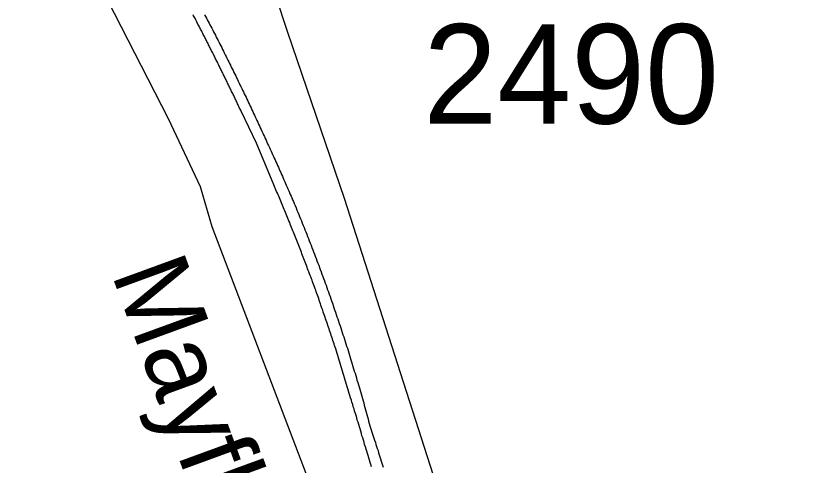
# Model space of a CAD drawing. Extents: x 1364363 to 1407445, y 538563 to 573342.
# Drawn here: x 1378365 to 1379352, y 550369 to 550934 of the extents above; entities that cross this region are included whole.
import ezdxf

# ---------------------------------------------------------------- set-up
doc = ezdxf.new("R2010")
doc.units = 0
for name, color, linetype in [('Exist Railroad Mainline', 7, 'Continuous'), ('Exist Railroad Siding', 7, 'Continuous'), ('Exist Road Secondary Type 51 Attributed', 7, 'Continuous'), ('Exist Road Secondary Type 51 Label', 7, 'Continuous'), ('Exist Road Secondary Type 51 Number Label', 7, 'Continuous')]:
    doc.layers.add(name, color=color, linetype=linetype)

msp = doc.modelspace()

# ---------------------------------------------------------------- linework, layer by layer
at = {"layer": 'Exist Railroad Mainline'}
for points in [[(1378649.02, 550814.08), (1378648.41, 550815.37), (1378647.79, 550816.7), (1378647.07, 550817.98), (1378646.46, 550819.31), (1378645.84, 550820.65), (1378645.23, 550821.93), (1378644.61, 550823.26), (1378644, 550824.54), (1378643.38, 550825.88), (1378642.77, 550827.21), (1378642.15, 550828.49), (1378641.54, 550829.82), (1378640.92, 550831.1), (1378640.21, 550832.44), (1378639.59, 550833.77), (1378638.98, 550835.05), (1378638.36, 550836.38), (1378637.74, 550837.67), (1378637.03, 550839), (1378636.41, 550840.33), (1378635.8, 550841.61), (1378635.08, 550842.95), (1378634.46, 550844.23), (1378633.85, 550845.56), (1378633.23, 550846.89), (1378632.62, 550848.17), (1378632, 550849.51), (1378631.39, 550850.79), (1378630.77, 550852.12), (1378630.16, 550853.35), (1378629.34, 550854.68), (1378628.72, 550856.02), (1378628.11, 550857.3), (1378627.49, 550858.63), (1378626.88, 550859.91), (1378626.26, 550861.25), (1378625.65, 550862.58), (1378624.83, 550863.86), (1378624.21, 550865.19), (1378623.6, 550866.42), (1378622.98, 550867.76), (1378622.37, 550869.04), (1378621.75, 550870.37), (1378621.03, 550871.7), (1378620.42, 550872.99), (1378619.7, 550874.32), (1378619.08, 550875.55), (1378618.47, 550876.88), (1378617.75, 550878.16), (1378617.14, 550879.5), (1378616.52, 550880.83), (1378615.91, 550882.11), (1378615.29, 550883.39), (1378614.47, 550884.67), (1378613.86, 550886.01), (1378613.24, 550887.29), (1378612.63, 550888.62), (1378611.91, 550889.85), (1378611.29, 550891.18), (1378610.58, 550892.52), (1378609.96, 550893.8), (1378609.24, 550895.08), (1378608.63, 550896.36), (1378608.01, 550897.69), (1378607.4, 550898.98), (1378606.58, 550900.31), (1378605.96, 550901.54), (1378605.35, 550902.87), (1378604.63, 550904.2), (1378604.01, 550905.44), (1378603.4, 550906.77), (1378602.78, 550908.05), (1378601.96, 550909.38), (1378601.35, 550910.61), (1378600.73, 550911.95), (1378600.02, 550913.23), (1378599.4, 550914.51), (1378598.78, 550915.79), (1378597.96, 550917.12), (1378597.35, 550918.46), (1378596.73, 550919.69), (1378596.02, 550921.02), (1378595.4, 550922.3), (1378594.58, 550923.58), (1378593.97, 550924.86), (1378593.35, 550926.2), (1378592.63, 550927.43), (1378592.02, 550928.76), (1378591.4, 550929.99), (1378590.58, 550931.32), (1378589.97, 550932.6), (1378589.25, 550933.89), (1378588.63, 550935.17)], [(1378690.14, 550721.45), (1378668.3, 550773.79), (1378649.02, 550814.08)], [(1378767.95, 550515.17), (1378767.24, 550517.32), (1378766.62, 550519.42), (1378765.9, 550521.48), (1378765.29, 550523.63), (1378764.47, 550525.73), (1378763.85, 550527.88), (1378763.13, 550529.98), (1378762.42, 550532.14), (1378761.8, 550534.19), (1378760.98, 550536.29), (1378760.26, 550538.44), (1378759.65, 550540.55), (1378758.83, 550542.7), (1378758.11, 550544.75), (1378757.5, 550546.85), (1378756.78, 550549), (1378755.96, 550551.11), (1378755.24, 550553.21), (1378754.52, 550555.31), (1378753.91, 550557.46), (1378753.09, 550559.51), (1378752.37, 550561.61), (1378751.65, 550563.77), (1378750.83, 550565.82), (1378750.11, 550567.92), (1378749.4, 550570.07), (1378748.78, 550572.12), (1378747.96, 550574.23), (1378747.24, 550576.33), (1378746.52, 550578.43), (1378745.7, 550580.58), (1378744.99, 550582.63), (1378744.27, 550584.73), (1378743.45, 550586.84), (1378742.73, 550588.94), (1378741.91, 550590.99), (1378741.09, 550593.14), (1378740.37, 550595.19), (1378739.66, 550597.29), (1378738.84, 550599.4), (1378738.12, 550601.5), (1378737.4, 550603.55), (1378736.58, 550605.7), (1378735.76, 550607.75), (1378735.04, 550609.8), (1378734.22, 550611.95), (1378733.5, 550614.01), (1378732.58, 550616.11), (1378731.86, 550618.21), (1378731.15, 550620.26), (1378730.22, 550622.36), (1378729.51, 550624.46), (1378728.79, 550626.51), (1378727.87, 550628.61), (1378727.15, 550630.67), (1378726.33, 550632.77), (1378725.51, 550634.82), (1378724.79, 550636.92), (1378723.87, 550639.02), (1378723.15, 550641.07), (1378722.33, 550643.12), (1378721.51, 550645.17), (1378720.79, 550647.33), (1378719.87, 550649.38), (1378719.05, 550651.43), (1378718.23, 550653.48), (1378717.41, 550655.58), (1378716.59, 550657.63), (1378715.77, 550659.73), (1378715.05, 550661.83), (1378714.13, 550663.88), (1378713.2, 550665.93), (1378712.49, 550667.98), (1378711.67, 550670.09), (1378710.74, 550672.14), (1378710.03, 550674.19), (1378709.1, 550676.24), (1378708.28, 550678.29), (1378707.36, 550680.39), (1378706.64, 550682.44), (1378705.72, 550684.49), (1378704.9, 550686.54), (1378703.98, 550688.64), (1378703.16, 550690.69), (1378702.34, 550692.75), (1378701.52, 550694.8), (1378700.59, 550696.79), (1378699.77, 550698.9), (1378698.85, 550700.95), (1378698.03, 550703), (1378697.11, 550705.05), (1378696.29, 550707.15), (1378695.36, 550709.15), (1378694.54, 550711.2), (1378693.62, 550713.25), (1378692.8, 550715.3), (1378691.88, 550717.35), (1378690.96, 550719.35), (1378690.14, 550721.45)], [(1378812.76, 550367.07), (1378812.04, 550369.89), (1378811.12, 550372.61), (1378810.3, 550375.43), (1378809.48, 550378.25), (1378808.66, 550381.07), (1378807.73, 550383.83), (1378806.91, 550386.6), (1378806.09, 550389.42), (1378805.27, 550392.24), (1378804.35, 550395.01), (1378803.63, 550397.83), (1378802.71, 550400.65), (1378801.89, 550403.42), (1378800.97, 550406.19), (1378800.25, 550409), (1378799.33, 550411.82), (1378798.51, 550414.64), (1378797.79, 550417.36), (1378796.87, 550420.18), (1378796.04, 550423), (1378795.12, 550425.82), (1378794.4, 550428.59), (1378793.48, 550431.35), (1378792.66, 550434.17), (1378791.74, 550436.94), (1378791.02, 550439.76), (1378790.1, 550442.58), (1378789.28, 550445.35), (1378788.36, 550448.12), (1378787.64, 550450.94), (1378786.72, 550453.76), (1378785.89, 550456.53), (1378784.97, 550459.29), (1378784.15, 550462.11), (1378783.33, 550464.88), (1378782.51, 550467.7), (1378781.59, 550470.52), (1378780.77, 550473.29), (1378779.85, 550476.06), (1378779.13, 550478.88), (1378778.21, 550481.7), (1378777.39, 550484.41), (1378776.46, 550487.23), (1378775.64, 550490.05), (1378774.92, 550492.82), (1378774, 550495.64), (1378773.08, 550498.46), (1378772.26, 550501.18), (1378771.34, 550503.99), (1378770.52, 550506.81), (1378769.8, 550509.58), (1378768.88, 550512.35), (1378767.95, 550515.17)]]:
    msp.add_lwpolyline(points, dxfattribs=at)
at = {"layer": 'Exist Railroad Siding'}
for points in [[(1378602.99, 550935.12), (1378604.12, 550933.01), (1378605.24, 550930.91), (1378606.37, 550928.86), (1378607.5, 550926.81), (1378608.63, 550924.71), (1378609.76, 550922.61), (1378610.99, 550920.56)], [(1378610.99, 550920.56), (1378612.11, 550918.3), (1378613.24, 550916.15), (1378614.37, 550913.94), (1378615.5, 550911.69), (1378616.62, 550909.49), (1378617.75, 550907.23), (1378618.88, 550905.08), (1378620.01, 550902.82), (1378621.14, 550900.62), (1378622.26, 550898.41), (1378623.39, 550896.21), (1378624.52, 550894), (1378625.54, 550891.75), (1378626.67, 550889.54), (1378627.8, 550887.29), (1378628.82, 550885.14), (1378629.95, 550882.88), (1378631.08, 550880.62), (1378632.21, 550878.42), (1378633.34, 550876.16), (1378634.36, 550874.01), (1378635.49, 550871.76), (1378636.62, 550869.5), (1378637.74, 550867.3), (1378638.77, 550865.04), (1378639.9, 550862.84), (1378641.03, 550860.63), (1378642.15, 550858.38), (1378643.08, 550856.12), (1378644.2, 550853.92), (1378645.33, 550851.71), (1378646.46, 550849.46), (1378647.48, 550847.25), (1378648.61, 550845), (1378649.74, 550842.74), (1378650.77, 550840.49), (1378651.89, 550838.23), (1378652.92, 550836.08), (1378654.05, 550833.82), (1378655.17, 550831.57), (1378656.1, 550829.31), (1378657.22, 550827.05), (1378658.25, 550824.8), (1378659.38, 550822.65), (1378660.4, 550820.39), (1378661.53, 550818.13), (1378662.45, 550815.88), (1378663.58, 550813.62), (1378664.61, 550811.37), (1378665.73, 550809.11), (1378666.76, 550806.86), (1378667.89, 550804.6), (1378668.91, 550802.4), (1378669.84, 550800.14), (1378670.96, 550797.89), (1378671.99, 550795.63), (1378673.12, 550793.37), (1378674.14, 550791.12), (1378675.17, 550788.86), (1378676.29, 550786.61), (1378677.22, 550784.35), (1378678.24, 550782.15), (1378679.37, 550779.89), (1378680.4, 550777.64), (1378681.42, 550775.33), (1378682.34, 550773.07), (1378683.47, 550770.82), (1378684.5, 550768.56), (1378685.52, 550766.31), (1378686.55, 550764.05), (1378687.67, 550761.8), (1378688.6, 550759.49), (1378689.62, 550757.23), (1378690.65, 550754.98), (1378691.67, 550752.77), (1378692.6, 550750.42), (1378693.72, 550748.21), (1378694.75, 550745.96), (1378695.77, 550743.7), (1378696.8, 550741.39), (1378697.72, 550739.14), (1378698.75, 550736.88), (1378699.77, 550734.58), (1378700.8, 550732.32), (1378701.72, 550730.06), (1378702.75, 550727.76), (1378703.77, 550725.5), (1378704.8, 550723.25), (1378705.72, 550720.94), (1378706.74, 550718.68), (1378707.77, 550716.38), (1378708.8, 550714.12), (1378709.72, 550711.87), (1378710.74, 550709.56), (1378711.77, 550707.3), (1378712.79, 550705), (1378713.61, 550702.74), (1378714.64, 550700.43), (1378715.66, 550698.18)], [(1378715.66, 550698.18), (1378716.79, 550695.46), (1378718.02, 550692.69), (1378719.15, 550689.87), (1378720.28, 550687.11), (1378721.41, 550684.39), (1378722.53, 550681.62), (1378723.66, 550678.85), (1378724.79, 550676.08), (1378725.92, 550673.32), (1378727.04, 550670.55), (1378728.17, 550667.83), (1378729.3, 550665.01), (1378730.33, 550662.24), (1378731.45, 550659.42), (1378732.48, 550656.71), (1378733.61, 550653.89), (1378734.73, 550651.12), (1378735.86, 550648.35), (1378736.89, 550645.58), (1378738.02, 550642.76), (1378739.04, 550640), (1378740.17, 550637.18), (1378741.3, 550634.46), (1378742.22, 550631.64), (1378743.35, 550628.82), (1378744.37, 550626.05), (1378745.4, 550623.23), (1378746.52, 550620.41), (1378747.55, 550617.64), (1378748.58, 550614.88), (1378749.6, 550612.06), (1378750.63, 550609.24), (1378751.65, 550606.42), (1378752.78, 550603.65), (1378753.7, 550600.83), (1378754.73, 550598.01), (1378755.75, 550595.24), (1378756.78, 550592.42), (1378757.7, 550589.6), (1378758.73, 550586.84), (1378759.75, 550584.02), (1378760.78, 550581.15), (1378761.8, 550578.33), (1378762.72, 550575.51), (1378763.75, 550572.69), (1378764.77, 550569.87), (1378765.59, 550567.05), (1378766.62, 550564.23), (1378767.65, 550561.36), (1378768.67, 550558.54), (1378769.49, 550555.77), (1378770.52, 550552.95), (1378771.54, 550550.08), (1378772.36, 550547.26), (1378773.39, 550544.44), (1378774.21, 550541.57), (1378775.23, 550538.75), (1378776.15, 550535.93), (1378777.08, 550533.06), (1378778, 550530.24), (1378778.92, 550527.37), (1378779.85, 550524.55), (1378780.77, 550521.68), (1378781.59, 550518.86), (1378782.61, 550515.99), (1378783.54, 550513.17), (1378784.36, 550510.3), (1378785.28, 550507.48), (1378786.1, 550504.61), (1378787.02, 550501.74), (1378787.84, 550498.92), (1378788.77, 550496.05), (1378789.59, 550493.18), (1378790.51, 550490.36), (1378791.33, 550487.49), (1378792.25, 550484.62), (1378793.17, 550481.75), (1378793.99, 550478.88), (1378794.71, 550476.06), (1378795.63, 550473.19), (1378796.46, 550470.31), (1378797.38, 550467.44), (1378798.1, 550464.57), (1378799.02, 550461.7), (1378799.84, 550458.83), (1378800.66, 550455.96), (1378801.48, 550453.04), (1378802.3, 550450.17), (1378803.12, 550447.3), (1378803.84, 550444.43), (1378804.66, 550441.56), (1378805.48, 550438.69), (1378806.3, 550435.82), (1378807.02, 550432.94), (1378807.84, 550430.07), (1378808.66, 550427.2), (1378809.37, 550424.33), (1378810.09, 550421.46), (1378811.01, 550418.49)], [(1378811.01, 550418.49), (1378811.73, 550415.93), (1378812.65, 550413.36), (1378813.47, 550410.75), (1378814.4, 550408.18), (1378815.22, 550405.57), (1378816.04, 550402.96), (1378816.86, 550400.39), (1378817.78, 550397.73), (1378818.6, 550395.16), (1378819.42, 550392.55), (1378820.24, 550389.99), (1378821.16, 550387.37), (1378821.88, 550384.76), (1378822.7, 550382.19), (1378823.62, 550379.58), (1378824.34, 550376.91), (1378825.26, 550374.35), (1378825.98, 550371.74), (1378826.91, 550369.12), (1378827.62, 550366.56)]]:
    msp.add_lwpolyline(points, dxfattribs=at)
at = {"layer": 'Exist Road Secondary Type 51 Attributed'}
for points in [[(1378382.35, 551904.12), (1378429.78, 551811.86), (1378473.75, 551674.16), (1378543.71, 551422.65), (1378610.69, 551208.68), (1378661.13, 551053.31), (1378707.39, 550913.34), (1378778.53, 550704.8), (1378942.41, 550194.7), (1378990.85, 550031.69), (1379059.72, 549823.15), (1379089.99, 549724.76), (1379170.92, 549598.91), (1379210.9, 549552.37), (1379251.99, 549499.77), (1379372.32, 549398.37), (1379560.73, 549245.93), (1379873.58, 548966.64), (1380066.49, 548794.03), (1380359.35, 548545.77), (1380481.29, 548439.1)], [(1378951.18, 549800.79), (1378862.52, 550016.26), (1378734.63, 550348.52), (1378612.69, 550668.54), (1378597.69, 550718.96), (1378557.71, 550804.3), (1378472.79, 550970.17), (1378342.33, 551169.16), (1378284.07, 551241.41), (1378232.69, 551282.48), (1378190.71, 551297.99), (1378118.15, 551299.71), (1378066.22, 551297.17), (1378009.22, 551285.77), (1377923.02, 551262.02), (1377875.53, 551244.79), (1377794.46, 551256.24), (1377751.89, 551264.22), (1377739.38, 551263.8), (1377704.55, 551251.12), (1377653.15, 551229.05), (1377610.17, 551217.41)]]:
    msp.add_lwpolyline(points, dxfattribs=at)

# ---------------------------------------------------------------- texts
at = {"layer": 'Exist Road Secondary Type 51 Label'}
msp.add_text('Mayflower', height=95, rotation=290.07943, dxfattribs=at).set_placement((1378485.44, 550610.16))
at = {"layer": 'Exist Road Secondary Type 51 Number Label'}
msp.add_text('2490', height=125, dxfattribs=at).set_placement((1378878.21, 550798.44))

doc.saveas('drawing.dxf')
